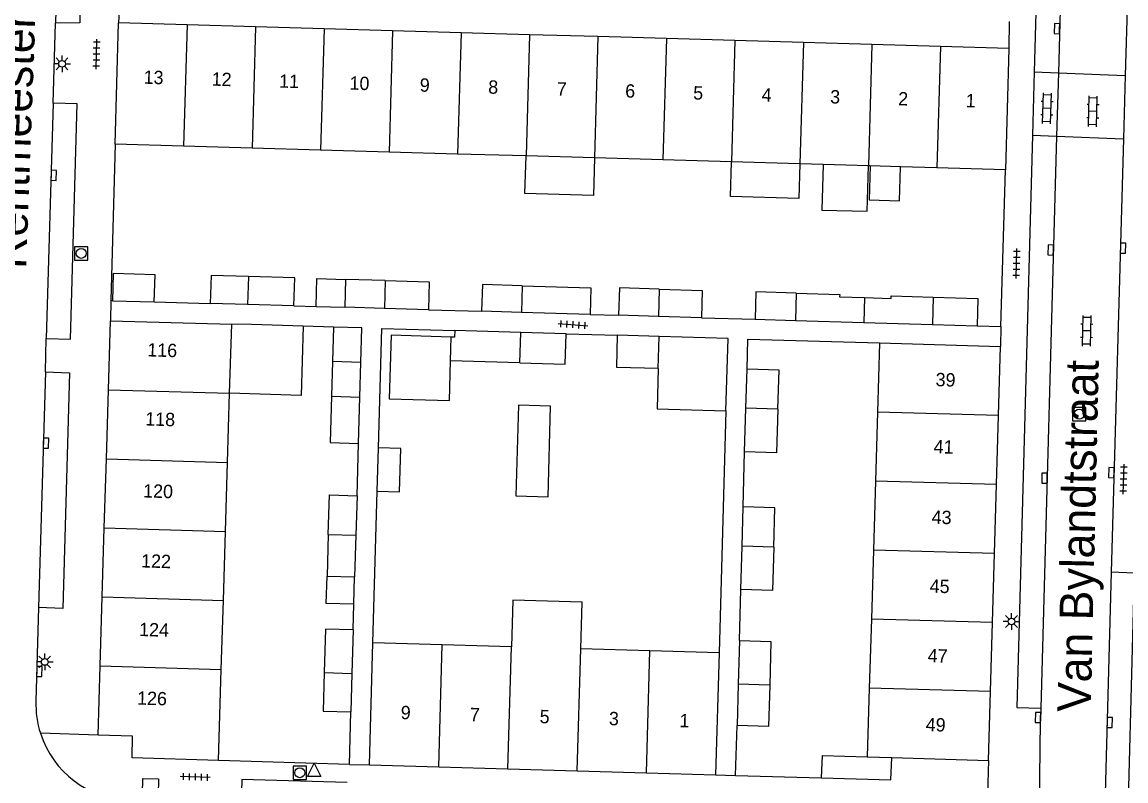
# Model space of a CAD drawing. Extents: x 132998 to 136004, y 396998 to 398512.
# Drawn here: x 133076.5 to 133159.2, y 397877.2 to 397934.1 of the extents above; entities that cross this region are included whole.
import ezdxf

# ---------------------------------------------------------------- set-up
doc = ezdxf.new("R2010")
doc.units = 0
for name, color, linetype in [('gg-afsc-erfafscheiding', 7, 'Continuous'), ('gg-afsc-hekwerk', 7, 'Continuous'), ('gg-anno-huisnummerreeks BGT', 7, 'Continuous'), ('gg-anno-openbare ruimte label', 7, 'Continuous'), ('gg-bbg-bijgebouw', 7, 'Continuous'), ('gg-bbg-gedigitaliseerde bebouwing', 7, 'Continuous'), ('gg-bbg-gedigitaliseerde bijgebouw', 7, 'Continuous'), ('gg-bbg-hoofdgebouw', 7, 'Continuous'), ('gg-bbg-luifel en loopbrug', 7, 'Continuous'), ('gg-bbg-tussenscheiding', 7, 'Continuous'), ('gg-knt-verharding', 7, 'Continuous'), ('gg-knt-verharding nz', 7, 'Continuous'), ('gt-grn-weggrens', 7, 'Continuous'), ('gt-symb-klinker verharding', 7, 'Continuous'), ('gt-symb-kolk', 7, 'Continuous'), ('gt-symb-lichtmast', 7, 'Continuous'), ('gt-symb-rioolschacht', 7, 'Continuous'), ('gt-symb-tegel verharding', 7, 'Continuous'), ('gt-symb-waterafsluiter', 7, 'Continuous')]:
    doc.layers.add(name, color=color, linetype=linetype)

# ---------------------------------------------------------------- blocks, each defined once
blk = doc.blocks.new('gt0-TEG1')
at = {"layer": 'gt-symb-tegel verharding'}
for p, q in [((-1.125, 0), (1.125, 0)), ((-0.9, -0.25), (-0.9, 0.25)), ((-0.45, -0.25), (-0.45, 0.25)), ((0, -0.25), (0, 0.25)), ((0.45, -0.25), (0.45, 0.25)), ((0.9, -0.25), (0.9, 0.25))]:
    blk.add_line(p, q, dxfattribs=at)
blk = doc.blocks.new('gt0-KOLK')
at = {"layer": 'gt-symb-kolk'}
blk.add_lwpolyline([(0, 0), (0.375, 0), (0.375, 0.4), (-0.375, 0.4), (-0.375, 0), (0, 0)], dxfattribs=at)
blk = doc.blocks.new('gt0-LMAST')
at = {"layer": 'gt-symb-lichtmast'}
for p, q in [((-0.182, 0.173), (-0.447, 0.438)), ((-0.005, 0.246), (-0.005, 0.621)), ((0.172, 0.173), (0.437, 0.438)), ((-0.255, -0.004), (-0.63, -0.004)), ((-0.182, -0.181), (-0.447, -0.446)), ((-0.005, -0.254), (-0.005, -0.629)), ((0.437, -0.446), (0.172, -0.181)), ((0.245, -0.004), (0.62, -0.004))]:
    blk.add_line(p, q, dxfattribs=at)
blk.add_circle((-0.005, -0.004), 0.25, dxfattribs=at)
blk = doc.blocks.new('gt0-RS')
at = {"layer": 'gt-symb-rioolschacht'}
blk.add_lwpolyline([(-0.5, -0.5), (0.5, -0.5), (0.5, 0.5), (-0.5, 0.5)], close=True, dxfattribs=at)
blk.add_circle((0, 0), 0.375, dxfattribs=at)
blk = doc.blocks.new('gt0-WAFSL')
at = {"layer": 'gt-symb-waterafsluiter'}
for p, q in [((-0.5, -0.333), (0, 0.667)), ((0, 0.667), (0.5, -0.333)), ((0.5, -0.333), (-0.5, -0.333))]:
    blk.add_line(p, q, dxfattribs=at)
blk = doc.blocks.new('gt0-KL1')
at = {"layer": 'gt-symb-klinker verharding'}
for p, q in [((-1.15, 0.3), (1.15, 0.3)), ((-1, -0.3), (-1, 0.3)), ((-0.5, 0.3), (-0.5, 0.45)), ((0, -0.3), (0, 0.3)), ((0.5, 0.3), (0.5, 0.45)), ((1, -0.3), (1, 0.3)), ((-1.15, -0.3), (1.15, -0.3)), ((-0.5, -0.45), (-0.5, -0.3)), ((0.5, -0.45), (0.5, -0.3))]:
    blk.add_line(p, q, dxfattribs=at)

msp = doc.modelspace()

# ---------------------------------------------------------------- linework, layer by layer
at = {"layer": 'gg-afsc-erfafscheiding'}
for p, q in [((133083.43, 397924.95), (133083.108, 397913.222)), ((133149.813, 397911.283), (133150.151, 397923.04)), ((133083.219, 397913.219), (133083.108, 397913.222)), ((133086.353, 397913.122), (133090.551, 397913.017)), ((133096.826, 397912.833), (133098.488, 397912.785)), ((133106.906, 397912.539), (133110.894, 397912.422)), ((133119.016, 397912.185), (133121.153, 397912.122)), ((133099.795, 397911.244), (133097.525, 397911.311)), ((133127.36, 397911.94), (133131.383, 397911.822)), ((133148.023, 397911.335), (133149.813, 397911.283)), ((133117.226, 397910.736), (133121.086, 397910.628)), ((133129.194, 397904.955), (133128.686, 397886.83)), ((133101.554, 397898.597), (133101.664, 397902.522)), ((133130.493, 397897.772), (133130.601, 397901.889)), ((133102.746, 397887.58), (133103.064, 397898.944)), ((133130.212, 397887.744), (133130.319, 397891.572)), ((133101.267, 397888.543), (133101.32, 397890.459)), ((133100.99, 397878.461), (133101.098, 397882.387)), ((133129.929, 397877.628), (133130.034, 397881.372)), ((133100.99, 397878.461), (133091.18, 397878.75)), ((133129.929, 397877.628), (133136.358, 397877.452))]:
    msp.add_line(p, q, dxfattribs=at)
for points in [[(133103.155, 397902.186), (133103.406, 397911.141), (133108.882, 397910.98)], [(133130.782, 397908.089), (133130.845, 397910.338), (133140.723, 397910.049)]]:
    msp.add_lwpolyline(points, dxfattribs=at)
at = {"layer": 'gg-afsc-hekwerk'}
for p, q in [((133083.108, 397913.222), (133083.07, 397911.72)), ((133149.813, 397911.283), (133149.77, 397909.78)), ((133100.99, 397878.461), (133102.49, 397878.42)), ((133128.43, 397877.67), (133129.929, 397877.628))]:
    msp.add_line(p, q, dxfattribs=at)
at = {"layer": 'gg-bbg-bijgebouw'}
msp.add_line((133083.219, 397913.219), (133086.353, 397913.122), dxfattribs=at)
msp.add_lwpolyline([(133086.353, 397913.122), (133086.417, 397915.161), (133083.276, 397915.256), (133083.219, 397913.219)], dxfattribs=at)
at = {"layer": 'gg-bbg-gedigitaliseerde bebouwing'}
for p, q in [((133088.561, 397924.803), (133083.43, 397924.95)), ((133093.693, 397924.656), (133088.561, 397924.803)), ((133098.825, 397924.509), (133093.693, 397924.656)), ((133103.957, 397924.362), (133098.825, 397924.509)), ((133109.089, 397924.215), (133103.957, 397924.362)), ((133114.221, 397924.069), (133109.089, 397924.215)), ((133119.353, 397923.922), (133114.221, 397924.069)), ((133124.485, 397923.775), (133119.353, 397923.922)), ((133129.617, 397923.628), (133124.485, 397923.775)), ((133134.749, 397923.481), (133129.617, 397923.628)), ((133136.495, 397923.431), (133134.749, 397923.481)), ((133139.881, 397923.334), (133136.495, 397923.431)), ((133140.021, 397923.33), (133139.881, 397923.334)), ((133142.282, 397923.265), (133140.021, 397923.33)), ((133145.013, 397923.187), (133142.282, 397923.265)), ((133150.151, 397923.04), (133145.013, 397923.187)), ((133092.006, 397906.276), (133092.162, 397911.456)), ((133140.723, 397910.049), (133140.567, 397904.867)), ((133140.723, 397910.049), (133149.77, 397909.78)), ((133091.851, 397901.1), (133092.006, 397906.276)), ((133140.567, 397904.867), (133140.412, 397899.695)), ((133091.695, 397895.923), (133091.851, 397901.1)), ((133140.412, 397899.695), (133140.256, 397894.523)), ((133091.54, 397890.746), (133091.695, 397895.923)), ((133140.256, 397894.523), (133140.101, 397889.352)), ((133091.385, 397885.569), (133091.54, 397890.746)), ((133140.101, 397889.352), (133139.945, 397884.18)), ((133102.49, 397878.42), (133102.746, 397887.58)), ((133107.943, 397887.43), (133102.746, 397887.58)), ((133113.131, 397887.28), (133107.943, 397887.43)), ((133123.506, 397886.98), (133118.318, 397887.13)), ((133128.686, 397886.83), (133123.506, 397886.98)), ((133128.686, 397886.83), (133128.43, 397877.67)), ((133091.18, 397878.75), (133091.385, 397885.569)), ((133139.945, 397884.18), (133139.79, 397879.02))]:
    msp.add_line(p, q, dxfattribs=at)
msp.add_lwpolyline([(133118.318, 397887.13), (133118.419, 397890.618), (133113.232, 397890.768), (133113.131, 397887.28)], dxfattribs=at)
at = {"layer": 'gg-bbg-gedigitaliseerde bijgebouw'}
for p, q in [((133100.693, 397914.808), (133100.632, 397912.722)), ((133103.675, 397914.72), (133100.693, 397914.808)), ((133093.356, 397912.935), (133090.551, 397913.017)), ((133096.826, 397912.833), (133093.356, 397912.935)), ((133103.614, 397912.635), (133100.632, 397912.722)), ((133106.906, 397912.539), (133103.614, 397912.635)), ((133113.878, 397912.335), (133110.894, 397912.422)), ((133119.016, 397912.185), (133113.878, 397912.335)), ((133124.141, 397912.034), (133121.153, 397912.122)), ((133127.36, 397911.94), (133124.141, 397912.034)), ((133131.383, 397911.822), (133134.412, 397911.733)), ((133134.412, 397911.733), (133139.544, 397911.583)), ((133139.544, 397911.583), (133144.676, 397911.433)), ((133144.676, 397911.433), (133148.023, 397911.335)), ((133113.82, 397910.836), (133108.882, 397910.98)), ((133117.226, 397910.736), (133113.82, 397910.836)), ((133124.195, 397910.534), (133121.086, 397910.628)), ((133099.723, 397908.648), (133099.65, 397906.052)), ((133101.833, 397908.587), (133099.723, 397908.648)), ((133113.754, 397908.566), (133108.566, 397908.718)), ((133101.761, 397905.991), (133101.833, 397908.587)), ((133130.696, 397905.156), (133130.782, 397908.089)), ((133101.664, 397902.522), (133101.761, 397905.991)), ((133130.601, 397901.889), (133130.696, 397905.156)), ((133101.554, 397898.597), (133101.467, 397895.637)), ((133130.41, 397894.811), (133130.493, 397897.772)), ((133099.402, 397895.697), (133099.311, 397892.575)), ((133101.467, 397895.637), (133101.376, 397892.514)), ((133130.319, 397891.572), (133130.41, 397894.811)), ((133099.311, 397892.575), (133101.376, 397892.514)), ((133101.267, 397888.543), (133101.177, 397885.282)), ((133130.212, 397887.744), (133130.12, 397884.461)), ((133101.177, 397885.282), (133101.098, 397882.387)), ((133130.12, 397884.461), (133130.034, 397881.372))]:
    msp.add_line(p, q, dxfattribs=at)
for points in [[(133093.416, 397915.022), (133090.612, 397915.105), (133090.551, 397913.017)], [(133096.826, 397912.833), (133096.887, 397914.92), (133093.416, 397915.022)], [(133103.675, 397914.72), (133106.967, 397914.624), (133106.906, 397912.539)], [(133113.936, 397914.34), (133110.953, 397914.428), (133110.894, 397912.422)], [(133113.936, 397914.34), (133119.074, 397914.19), (133119.016, 397912.185)], [(133124.201, 397914.087), (133121.213, 397914.174), (133121.153, 397912.122)], [(133124.201, 397914.087), (133127.42, 397913.993), (133127.36, 397911.94)], [(133134.471, 397913.787), (133131.443, 397913.876), (133131.383, 397911.822)], [(133134.471, 397913.787), (133137.729, 397913.692), (133137.723, 397913.505), (133139.597, 397913.45)], [(133139.597, 397913.45), (133141.579, 397913.392), (133141.584, 397913.579), (133144.734, 397913.487)], [(133144.734, 397913.487), (133148.083, 397913.389), (133148.023, 397911.335)], [(133108.618, 397910.495), (133104.113, 397910.628), (133103.974, 397905.872), (133108.479, 397905.74), (133108.566, 397908.718)], [(133108.882, 397910.98), (133108.868, 397910.488), (133108.618, 397910.495)], [(133113.754, 397908.566), (133117.16, 397908.467), (133117.226, 397910.736)], [(133124.125, 397908.126), (133121.016, 397908.217), (133121.086, 397910.628)], [(133129.194, 397904.955), (133129.357, 397910.379), (133124.195, 397910.534)], [(133124.125, 397908.126), (133124.037, 397905.105), (133129.194, 397904.955)], [(133133.098, 397905.086), (133133.184, 397908.018), (133130.782, 397908.089)], [(133099.65, 397906.052), (133099.553, 397902.584), (133101.664, 397902.522)], [(133115.867, 397898.518), (133116.065, 397905.319), (133113.662, 397905.388), (133113.464, 397898.588), (133115.867, 397898.518)], [(133133.098, 397905.086), (133133.003, 397901.818), (133130.601, 397901.889)], [(133099.402, 397895.697), (133099.489, 397898.657), (133101.554, 397898.597)], [(133132.783, 397894.742), (133132.87, 397897.702), (133130.493, 397897.772)], [(133132.783, 397894.742), (133132.688, 397891.502), (133130.319, 397891.572)], [(133101.267, 397888.543), (133099.195, 397888.6), (133099.1, 397885.343)], [(133130.212, 397887.744), (133132.576, 397887.677), (133132.48, 397884.394)], [(133099.1, 397885.343), (133099.016, 397882.444), (133101.098, 397882.387)], [(133132.48, 397884.394), (133132.389, 397881.306), (133130.034, 397881.372)], [(133136.358, 397877.452), (133136.44, 397879.119), (133139.79, 397879.02)], [(133136.358, 397877.452), (133141.56, 397877.31), (133141.641, 397878.965)]]:
    msp.add_lwpolyline(points, dxfattribs=at)
at = {"layer": 'gg-bbg-hoofdgebouw'}
for p, q in [((133083.43, 397924.95), (133083.69, 397934.04)), ((133088.822, 397933.893), (133083.69, 397934.04)), ((133093.954, 397933.746), (133088.822, 397933.893)), ((133099.086, 397933.599), (133093.954, 397933.746)), ((133104.218, 397933.452), (133099.086, 397933.599)), ((133109.35, 397933.305), (133104.218, 397933.452)), ((133114.482, 397933.159), (133109.35, 397933.305)), ((133119.614, 397933.012), (133114.482, 397933.159)), ((133124.746, 397932.865), (133119.614, 397933.012)), ((133129.878, 397932.718), (133124.746, 397932.865)), ((133135.01, 397932.571), (133129.878, 397932.718)), ((133140.142, 397932.424), (133135.01, 397932.571)), ((133145.274, 397932.277), (133140.142, 397932.424)), ((133150.41, 397932.13), (133145.274, 397932.277)), ((133150.41, 397932.13), (133150.151, 397923.04)), ((133082.918, 397906.543), (133083.07, 397911.72)), ((133083.07, 397911.72), (133092.162, 397911.456)), ((133149.622, 397904.608), (133149.77, 397909.78)), ((133082.767, 397901.366), (133082.918, 397906.543)), ((133149.473, 397899.436), (133149.622, 397904.608)), ((133082.615, 397896.189), (133082.767, 397901.366)), ((133149.325, 397894.264), (133149.473, 397899.436)), ((133082.463, 397891.012), (133082.615, 397896.189)), ((133149.177, 397889.092), (133149.325, 397894.264)), ((133082.312, 397885.835), (133082.463, 397891.012)), ((133149.028, 397883.92), (133149.177, 397889.092)), ((133082.16, 397880.66), (133082.312, 397885.835)), ((133148.88, 397878.75), (133149.028, 397883.92)), ((133141.641, 397878.965), (133148.88, 397878.75)), ((133102.49, 397878.42), (133107.678, 397878.27)), ((133107.678, 397878.27), (133112.866, 397878.12)), ((133112.866, 397878.12), (133118.054, 397877.97)), ((133118.054, 397877.97), (133123.242, 397877.82)), ((133123.242, 397877.82), (133128.43, 397877.67))]:
    msp.add_line(p, q, dxfattribs=at)
msp.add_lwpolyline([(133091.18, 397878.75), (133084.71, 397878.95), (133084.72, 397880.58), (133082.16, 397880.66)], dxfattribs=at)
at = {"layer": 'gg-bbg-luifel en loopbrug'}
for p, q in [((133098.488, 397912.785), (133100.632, 397912.722)), ((133099.795, 397911.244), (133099.723, 397908.648)), ((133103.064, 397898.944), (133103.155, 397902.186)), ((133101.32, 397890.459), (133101.376, 397892.514))]:
    msp.add_line(p, q, dxfattribs=at)
for points in [[(133119.353, 397923.922), (133119.272, 397921.102), (133114.14, 397921.249), (133114.221, 397924.069)], [(133134.749, 397923.481), (133134.674, 397920.883), (133129.542, 397921.03), (133129.617, 397923.628)], [(133136.495, 397923.431), (133136.397, 397920.015), (133139.783, 397919.918), (133139.881, 397923.334)], [(133140.021, 397923.33), (133139.947, 397920.776), (133142.209, 397920.712), (133142.282, 397923.265)], [(133098.488, 397912.785), (133098.548, 397914.871), (133100.693, 397914.808)], [(133097.525, 397911.311), (133097.369, 397906.118), (133092.006, 397906.276)], [(133097.525, 397911.311), (133093.655, 397911.426), (133092.162, 397911.456)], [(133101.833, 397908.587), (133101.906, 397911.185), (133099.795, 397911.244)], [(133103.064, 397898.944), (133104.738, 397898.897), (133104.828, 397902.14), (133103.155, 397902.186)], [(133101.32, 397890.459), (133099.251, 397890.52), (133099.311, 397892.575)]]:
    msp.add_lwpolyline(points, dxfattribs=at)
at = {"layer": 'gg-bbg-tussenscheiding'}
for p, q in [((133088.822, 397933.893), (133088.561, 397924.803)), ((133093.954, 397933.746), (133093.693, 397924.656)), ((133099.086, 397933.599), (133098.825, 397924.509)), ((133104.218, 397933.452), (133103.957, 397924.362)), ((133109.35, 397933.305), (133109.089, 397924.215)), ((133114.482, 397933.159), (133114.221, 397924.069)), ((133119.614, 397933.012), (133119.353, 397923.922)), ((133124.746, 397932.865), (133124.485, 397923.775)), ((133129.878, 397932.718), (133129.617, 397923.628)), ((133135.01, 397932.571), (133134.749, 397923.481)), ((133140.142, 397932.424), (133139.881, 397923.334)), ((133145.274, 397932.277), (133145.013, 397923.187)), ((133093.416, 397915.022), (133093.356, 397912.935)), ((133103.675, 397914.72), (133103.614, 397912.635)), ((133113.936, 397914.34), (133113.878, 397912.335)), ((133124.201, 397914.087), (133124.141, 397912.034)), ((133134.471, 397913.787), (133134.412, 397911.733)), ((133139.597, 397913.45), (133139.544, 397911.583)), ((133144.734, 397913.487), (133144.676, 397911.433)), ((133108.566, 397908.718), (133108.618, 397910.495)), ((133113.754, 397908.566), (133113.82, 397910.836)), ((133124.125, 397908.126), (133124.195, 397910.534)), ((133082.918, 397906.543), (133092.006, 397906.276)), ((133099.65, 397906.052), (133101.761, 397905.991)), ((133133.098, 397905.086), (133130.696, 397905.156)), ((133149.622, 397904.608), (133140.567, 397904.867)), ((133082.767, 397901.366), (133091.851, 397901.1)), ((133149.473, 397899.436), (133140.412, 397899.695)), ((133082.615, 397896.189), (133091.695, 397895.923)), ((133099.402, 397895.697), (133101.467, 397895.637)), ((133132.783, 397894.742), (133130.41, 397894.811)), ((133149.325, 397894.264), (133140.256, 397894.523)), ((133082.463, 397891.012), (133091.54, 397890.746)), ((133149.177, 397889.092), (133140.101, 397889.352)), ((133107.678, 397878.27), (133107.943, 397887.43)), ((133112.866, 397878.12), (133113.131, 397887.28)), ((133118.054, 397877.97), (133118.318, 397887.13)), ((133123.242, 397877.82), (133123.506, 397886.98)), ((133082.312, 397885.835), (133091.385, 397885.569)), ((133099.1, 397885.343), (133101.177, 397885.282)), ((133132.48, 397884.394), (133130.12, 397884.461)), ((133149.028, 397883.92), (133139.945, 397884.18)), ((133139.79, 397879.02), (133141.641, 397878.965))]:
    msp.add_line(p, q, dxfattribs=at)
at = {"layer": 'gg-knt-verharding'}
for p, q in [((133159.431, 397940.983), (133159.126, 397930.112)), ((133083.79, 397935.98), (133083.69, 397934.04)), ((133078.776, 397928.025), (133078.948, 397934.018)), ((133150.42, 397934.16), (133150.41, 397932.13)), ((133152.308, 397930.372), (133152.177, 397925.624)), ((133152.308, 397930.372), (133154.116, 397930.303)), ((133154.116, 397930.303), (133159.126, 397930.112)), ((133159.126, 397930.112), (133158.993, 397925.364)), ((133152.177, 397925.624), (133153.985, 397925.555)), ((133153.985, 397925.555), (133158.993, 397925.364)), ((133158.993, 397925.364), (133158.08, 397892.86)), ((133078.198, 397907.891), (133078.27, 397910.38)), ((133077.69, 397890.208), (133077.489, 397883.2)), ((133152.8, 397882.684), (133152.773, 397881.712)), ((133152.689, 397873.931), (133152.773, 397881.712))]:
    msp.add_line(p, q, dxfattribs=at)
for points in [[(133154.778, 397954.269), (133152.97, 397954.4), (133152.308, 397930.372)], [(133080.912, 397940.662), (133080.79, 397934.048), (133078.948, 397934.018)], [(133078.27, 397910.38), (133080.083, 397910.33), (133080.577, 397927.972), (133078.776, 397928.025)], [(133152.177, 397925.624), (133150.995, 397882.713), (133152.8, 397882.684)], [(133078.198, 397907.891), (133080.012, 397907.813), (133079.515, 397890.148), (133077.69, 397890.208)], [(133157.416, 397869.238), (133159.197, 397869.198), (133159.833, 397892.79), (133158.08, 397892.86)], [(133085.467, 397876.222), (133085.494, 397877.41), (133086.679, 397877.37), (133086.652, 397876.182), (133085.467, 397876.222)], [(133100.822, 397877.098), (133092.934, 397877.334), (133092.879, 397875.509)]]:
    msp.add_lwpolyline(points, dxfattribs=at)
for centre, radius, start, end in [((133084.734, 397882.99), 7.248, 178.34182, 197.67201), ((133084.731, 397882.99), 7.245, 197.67519, 267.96407)]:
    msp.add_arc(centre, radius, start, end, dxfattribs=at)
at = {"layer": 'gg-knt-verharding nz'}
for p, q in [((133154.778, 397954.269), (133154.116, 397930.303)), ((133079.133, 397940.451), (133078.948, 397934.018)), ((133154.116, 397930.303), (133153.985, 397925.555)), ((133078.776, 397928.025), (133078.27, 397910.38)), ((133153.985, 397925.555), (133152.8, 397882.684)), ((133078.198, 397907.891), (133077.69, 397890.208)), ((133158.08, 397892.86), (133157.416, 397869.238))]:
    msp.add_line(p, q, dxfattribs=at)
at = {"layer": 'gt-grn-weggrens'}
for p, q in [((133082.16, 397880.66), (133077.828, 397880.79)), ((133148.88, 397878.75), (133148.737, 397873.981))]:
    msp.add_line(p, q, dxfattribs=at)

# ---------------------------------------------------------------- block references
at = {"layer": 'gt-symb-klinker verharding'}
for p, rotation in [((133153.258, 397927.638), 88.39613722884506), ((133156.701, 397927.413), 88.39613722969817), ((133156.246, 397910.956), 88.39613722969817)]:
    msp.add_blockref('gt0-KL1', p, dxfattribs=dict(at, rotation=rotation))
at = {"layer": 'gt-symb-kolk'}
for p, rotation in [((133154.207, 397933.602), 88.39613722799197), ((133078.62, 397922.627), -91.66111204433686), ((133153.749, 397917.011), 88.39613722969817), ((133158.762, 397917.159), -91.60386277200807), ((133078.044, 397902.543), -91.66111204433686), ((133158.288, 397900.317), 88.39613722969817), ((133153.276, 397899.907), 88.39613722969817), ((133077.552, 397885.429), -91.66111204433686), ((133152.78, 397881.964), 88.33888795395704), ((133157.764, 397881.603), -91.60386277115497)]:
    msp.add_blockref('gt0-KOLK', p, dxfattribs=dict(at, rotation=rotation))
at = {"layer": 'gt-symb-lichtmast', "rotation": 180}
for p in [(133079.44, 397930.968), (133078.144, 397886.13)]:
    msp.add_blockref('gt0-LMAST', p, dxfattribs=at)
at = {"layer": 'gt-symb-lichtmast'}
msp.add_blockref('gt0-LMAST', (133150.613, 397889.177), dxfattribs=at)
at = {"layer": 'gt-symb-rioolschacht'}
for p in [(133080.884, 397916.766), (133155.679, 397904.711), (133097.261, 397877.833)]:
    msp.add_blockref('gt0-RS', p, dxfattribs=at)
at = {"layer": 'gt-symb-tegel verharding'}
for p, rotation in [((133082.03, 397931.701), 88.96878732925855), ((133150.982, 397916.007), 88.33888795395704), ((133117.743, 397911.422), -4.530520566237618), ((133159.006, 397899.842), 88.39613722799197), ((133089.424, 397877.515), 178.22439947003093)]:
    msp.add_blockref('gt0-TEG1', p, dxfattribs=dict(at, rotation=rotation))
at = {"layer": 'gt-symb-waterafsluiter'}
msp.add_blockref('gt0-WAFSL', (133098.345, 397877.893), dxfattribs=at)

# ---------------------------------------------------------------- texts
at = {"layer": 'gg-anno-huisnummerreeks BGT'}
for s, rotation, p in [('13', 358.3, (133085.55, 397929.485)), ('12', 358.3, (133090.65, 397929.339)), ('11', 358.3, (133095.708, 397929.194)), ('10', 358.3, (133100.983, 397929.043)), ('9', 358.3, (133106.245, 397928.893)), ('8', 358.4, (133111.377, 397928.745)), ('7', 358.3, (133116.513, 397928.6)), ('6', 358.3, (133121.641, 397928.453)), ('5', 358.3, (133126.737, 397928.307)), ('4', 358.3, (133131.869, 397928.16)), ('3', 358.3, (133137.001, 397928.013)), ('2', 358.3, (133142.1, 397927.867)), ('1', 358.3, (133147.16, 397927.722)), ('116', 358.3, (133085.828, 397909.044)), ('39', 358.3, (133144.906, 397906.814)), ('118', 358.3, (133085.676, 397903.868)), ('41', 358.3, (133144.762, 397901.786)), ('120', 358.3, (133085.518, 397898.472)), ('43', 358.3, (133144.61, 397896.506)), ('122', 358.3, (133085.364, 397893.226)), ('45', 358.3, (133144.462, 397891.334)), ('124', 358.3, (133085.214, 397888.082)), ('47', 358.3, (133144.313, 397886.122)), ('126', 358.3, (133085.063, 397882.941)), ('9', 358.3, (133104.82, 397881.855)), ('7', 358.3, (133110.004, 397881.705)), ('5', 358.3, (133115.232, 397881.554)), ('3', 358.3, (133120.42, 397881.404)), ('1', 358.3, (133125.715, 397881.251)), ('49', 358.3, (133144.164, 397880.955))]:
    msp.add_text(s, height=1, rotation=rotation, dxfattribs=at).set_placement(p)
at = {"layer": 'gg-anno-openbare ruimte label'}
for s, rotation, p in [('Rentmeesterlaan', 87.9, (133076.751, 397915.581)), ('Van Bylandtstraat', 88.7, (133156.541, 397882.359))]:
    msp.add_text(s, height=2.5, rotation=rotation, dxfattribs=at).set_placement(p)

doc.saveas('drawing.dxf')
